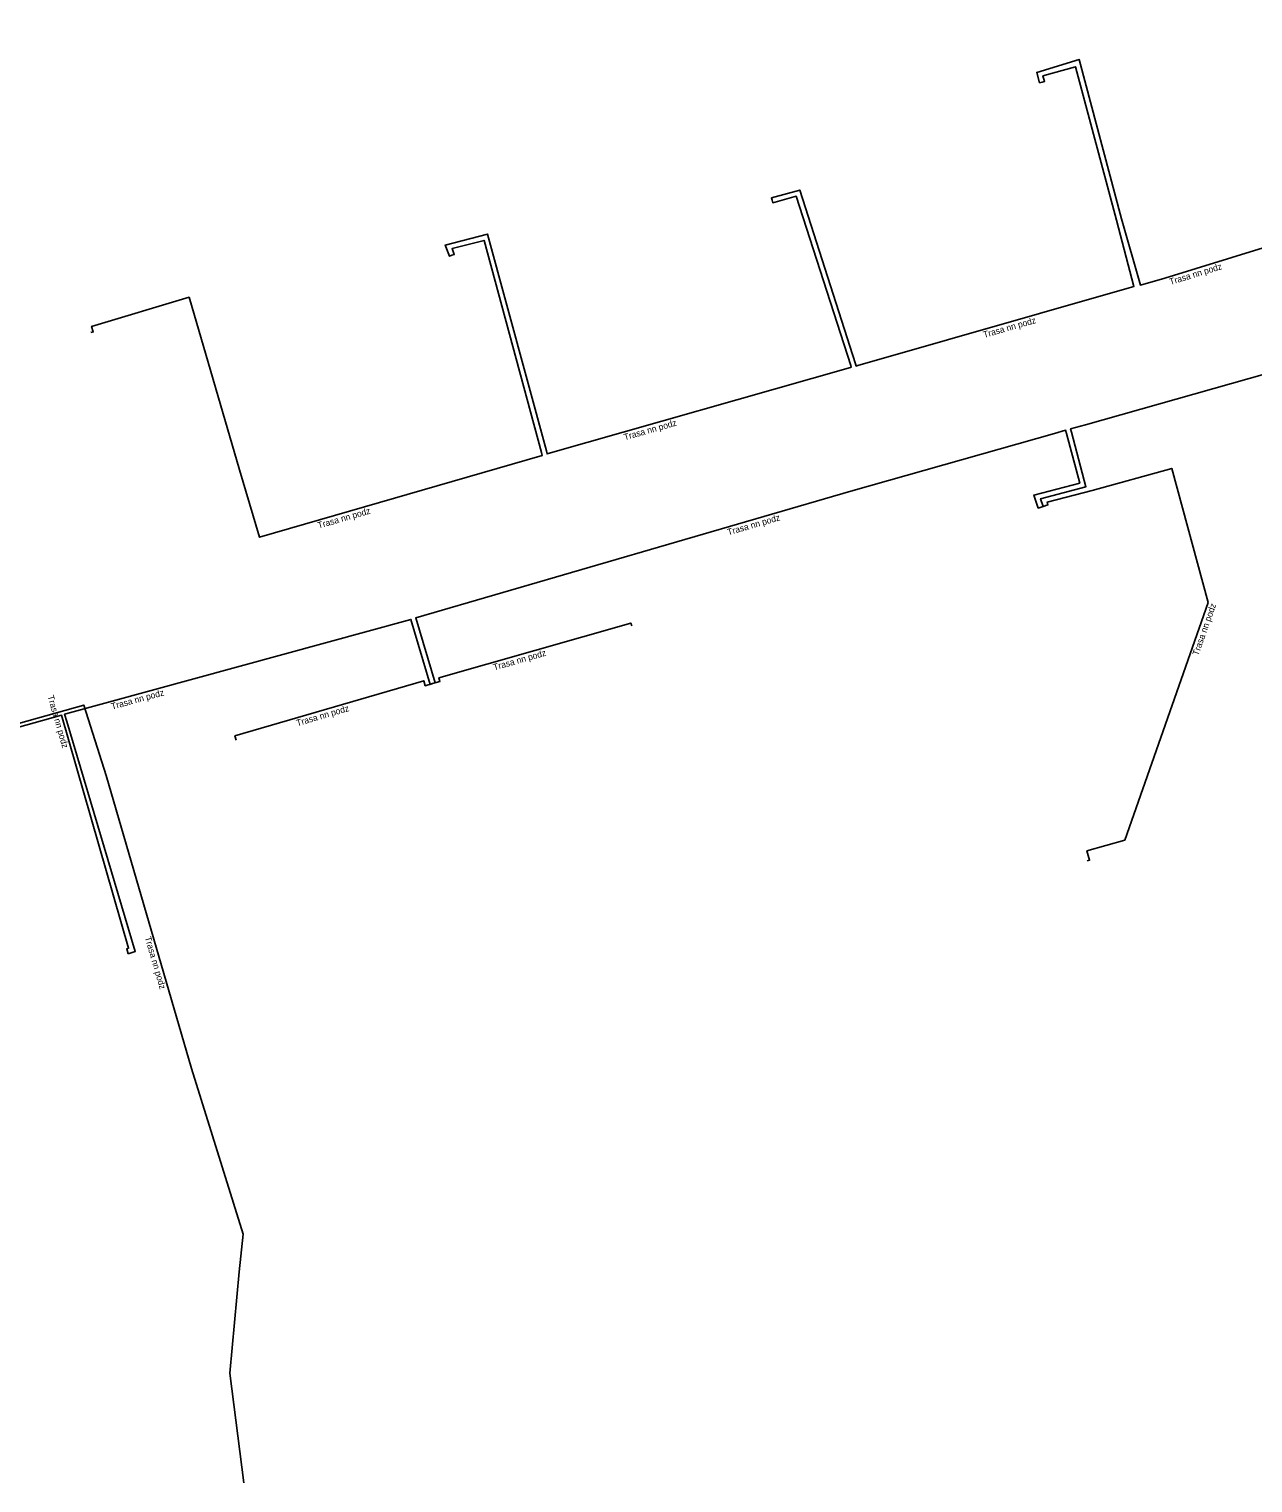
# Model space of a CAD drawing. Extents: x -690200 to -689130, y -975255 to -974631.
# Drawn here: x -689459.1 to -689363.1, y -974945.2 to -974831.2 of the extents above; entities that cross this region are included whole.
import ezdxf

# ---------------------------------------------------------------- set-up
doc = ezdxf.new("R2010")
doc.units = 0
doc.layers.add('Popiskový text - Ostatní atributy Trasy', color=7, linetype='Continuous')
doc.layers.add('Spojnice NN', color=7, linetype='Continuous')

msp = doc.modelspace()

# ---------------------------------------------------------------- linework, layer by layer
at = {"layer": 'Spojnice NN'}
for points in [[(-689359.16, -974831.24), (-689354.53, -974845.85), (-689354.49, -974846), (-689354.56, -974846.02), (-689370, -974850.76), (-689371.91, -974851.31), (-689373.4, -974846.11), (-689376.72, -974833.61), (-689380.04, -974834.63), (-689379.81, -974835.45), (-689379.61, -974835.4)], [(-689379.61, -974835.4), (-689379.42, -974835.34), (-689379.55, -974834.91), (-689376.99, -974834.19), (-689373.79, -974846.21), (-689372.42, -974851.41), (-689372.79, -974851.51), (-689394.06, -974857.61), (-689394.19, -974857.65), (-689394.24, -974857.48), (-689398.62, -974843.86), (-689400.84, -974844.46), (-689400.79, -974844.65)], [(-689425.91, -974848.97), (-689426.1, -974849.04), (-689426.42, -974848.17), (-689423.1, -974847.31), (-689418.49, -974864.31), (-689418.43, -974864.54), (-689418.35, -974864.52), (-689394.65, -974857.77), (-689394.58, -974857.74), (-689394.62, -974857.6), (-689398.89, -974844.34), (-689400.74, -974844.85), (-689400.79, -974844.65)], [(-689425.91, -974848.97), (-689425.72, -974848.9), (-689425.89, -974848.44), (-689423.38, -974847.8), (-689418.88, -974864.42), (-689418.81, -974864.66), (-689440.99, -974871.07), (-689442.56, -974865.78), (-689446.51, -974852.26), (-689454.16, -974854.54), (-689454.03, -974854.98), (-689454.22, -974855.03)], [(-689340.59, -974867.99), (-689340.66, -974867.8), (-689340.24, -974867.65), (-689344.27, -974853.61), (-689344.38, -974853.25), (-689344.82, -974853.37), (-689376.22, -974862.25), (-689377.38, -974862.58), (-689377.32, -974862.83), (-689376.18, -974867.12), (-689379.74, -974868.05), (-689379.54, -974868.67)], [(-689379.54, -974868.67), (-689379.92, -974868.79), (-689380.26, -974867.77), (-689376.67, -974866.83), (-689377.7, -974862.93), (-689377.77, -974862.69), (-689378.65, -974862.94), (-689394.62, -974867.46), (-689428.74, -974877.39), (-689427.22, -974882.49), (-689427.41, -974882.55)], [(-689379.54, -974868.67), (-689379.16, -974868.54), (-689379.23, -974868.33), (-689375.69, -974867.4), (-689369.45, -974865.68), (-689366.59, -974876.2), (-689373.13, -974894.81), (-689376.1, -974895.66), (-689375.89, -974896.39), (-689376.08, -974896.45)], [(-689451.28, -974903.72), (-689451.05, -974903.65), (-689450.73, -974903.55), (-689456.11, -974885.52), (-689456.28, -974884.94), (-689456.17, -974884.91), (-689429.11, -974877.52), (-689427.6, -974882.61), (-689427.41, -974882.55)], [(-689411.8, -974878.01), (-689411.88, -974877.8), (-689426.92, -974882.09), (-689426.84, -974882.38), (-689427.41, -974882.55)], [(-689427.41, -974882.55), (-689427.99, -974882.72), (-689428.11, -974882.32), (-689442.92, -974886.65), (-689442.82, -974886.97)], [(-689442.21, -974945.21), (-689443.31, -974936.6), (-689442.58, -974928.65), (-689442.27, -974925.7), (-689446.32, -974912.72), (-689453.01, -974889.76), (-689454.77, -974884.23), (-689471.65, -974888.96), (-689472.15, -974889.12), (-689472.06, -974889.42), (-689472.63, -974889.6)], [(-689472.63, -974889.6), (-689471.67, -974889.3), (-689471.55, -974889.22), (-689456.51, -974885.03), (-689451.25, -974903.29), (-689451.4, -974903.34), (-689451.28, -974903.72)]]:
    msp.add_lwpolyline(points, dxfattribs=at)

# ---------------------------------------------------------------- texts
at = {"layer": 'Popiskový text - Ostatní atributy Trasy'}
for rotation, p in [(17.0571, (-689369.55, -974851.3)), (15.9962, (-689384.16, -974855.45)), (15.9007, (-689412.34, -974863.48)), (16.1352, (-689436.35, -974870.4)), (16.2287, (-689404.22, -974870.93)), (70.6258, (-689367.37, -974880.39)), (15.9202, (-689422.58, -974881.52)), (286.0825, (-689457.62, -974883.54)), (15.2777, (-689452.55, -974884.59)), (16.2959, (-689438.02, -974885.89)), (286.2297, (-689449.99, -974902.45))]:
    msp.add_text('Trasa nn podz', height=0.5, rotation=rotation, dxfattribs=at).set_placement(p)

doc.saveas('drawing.dxf')
